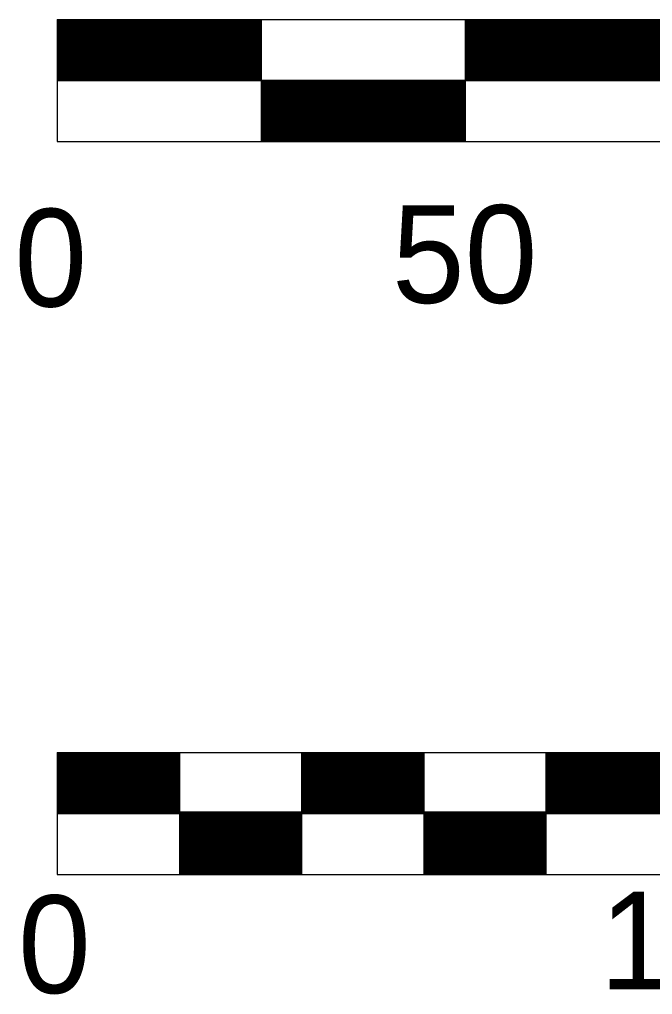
# Model space of a CAD drawing. Extents: x 2147712 to 2176316, y 2125036 to 2131746.
# Drawn here: x 2169958.2 to 2170010, y 2129019.9 to 2129099.7 of the extents above; entities that cross this region are included whole.
import ezdxf

# ---------------------------------------------------------------- set-up
doc = ezdxf.new("R2010")
doc.units = 0
doc.layers.add('MAP DATA', color=7, linetype='Continuous')

msp = doc.modelspace()

# ---------------------------------------------------------------- linework, layer by layer
at = {"layer": 'MAP DATA'}
for p, q in [((2169961.289, 2129099.718), (2170461.289, 2129099.718)), ((2169961.289, 2129099.718), (2169961.289, 2129089.718)), ((2169961.289, 2129099.618), (2169977.989, 2129099.618)), ((2169961.289, 2129099.518), (2169977.989, 2129099.518)), ((2169961.289, 2129099.418), (2169977.989, 2129099.418)), ((2169961.289, 2129099.318), (2169977.989, 2129099.318)), ((2169961.289, 2129099.218), (2169977.989, 2129099.218)), ((2169977.989, 2129099.718), (2169977.989, 2129089.718)), ((2169994.689, 2129099.718), (2169994.689, 2129089.718)), ((2169994.689, 2129099.718), (2170011.289, 2129099.718)), ((2169994.689, 2129099.618), (2170011.289, 2129099.618)), ((2169994.689, 2129099.518), (2170011.289, 2129099.518)), ((2169994.689, 2129099.418), (2170011.289, 2129099.418)), ((2169994.689, 2129099.318), (2170011.289, 2129099.318)), ((2169994.689, 2129099.218), (2170011.289, 2129099.218)), ((2169961.289, 2129099.118), (2169977.989, 2129099.118)), ((2169961.289, 2129099.018), (2169977.989, 2129099.018)), ((2169961.289, 2129098.918), (2169977.989, 2129098.918)), ((2169961.289, 2129098.818), (2169977.989, 2129098.818)), ((2169961.289, 2129098.718), (2169977.989, 2129098.718)), ((2169961.289, 2129098.618), (2169977.989, 2129098.618)), ((2169961.289, 2129098.518), (2169977.989, 2129098.518)), ((2169961.289, 2129098.418), (2169977.989, 2129098.418)), ((2169994.689, 2129099.118), (2170011.289, 2129099.118)), ((2169994.689, 2129099.018), (2170011.289, 2129099.018)), ((2169994.689, 2129098.918), (2170011.289, 2129098.918)), ((2169994.689, 2129098.818), (2170011.289, 2129098.818)), ((2169994.689, 2129098.718), (2170011.289, 2129098.718)), ((2169994.689, 2129098.618), (2170011.289, 2129098.618)), ((2169994.689, 2129098.518), (2170011.289, 2129098.518)), ((2169994.689, 2129098.418), (2170011.289, 2129098.418)), ((2169961.289, 2129098.318), (2169977.989, 2129098.318)), ((2169961.289, 2129098.218), (2169977.989, 2129098.218)), ((2169961.289, 2129098.118), (2169977.989, 2129098.118)), ((2169961.289, 2129098.018), (2169977.989, 2129098.018)), ((2169961.289, 2129097.918), (2169977.989, 2129097.918)), ((2169961.289, 2129097.818), (2169977.989, 2129097.818)), ((2169961.289, 2129097.718), (2169977.989, 2129097.718)), ((2169961.289, 2129097.618), (2169977.989, 2129097.618)), ((2169994.689, 2129098.318), (2170011.289, 2129098.318)), ((2169994.689, 2129098.218), (2170011.289, 2129098.218)), ((2169994.689, 2129098.118), (2170011.289, 2129098.118)), ((2169994.689, 2129098.018), (2170011.289, 2129098.018)), ((2169994.689, 2129097.918), (2170011.289, 2129097.918)), ((2169994.689, 2129097.818), (2170011.289, 2129097.818)), ((2169994.689, 2129097.718), (2170011.289, 2129097.718)), ((2169994.689, 2129097.618), (2170011.289, 2129097.618)), ((2169961.289, 2129097.518), (2169977.989, 2129097.518)), ((2169961.289, 2129097.418), (2169977.989, 2129097.418)), ((2169961.289, 2129097.318), (2169977.989, 2129097.318)), ((2169961.289, 2129097.218), (2169977.989, 2129097.218)), ((2169961.289, 2129097.118), (2169977.989, 2129097.118)), ((2169961.289, 2129097.018), (2169977.989, 2129097.018)), ((2169961.289, 2129096.918), (2169977.989, 2129096.918)), ((2169961.289, 2129096.918), (2169977.989, 2129096.918)), ((2169961.289, 2129096.818), (2169977.989, 2129096.818)), ((2169961.289, 2129096.818), (2169977.989, 2129096.818)), ((2169994.689, 2129097.518), (2170011.289, 2129097.518)), ((2169994.689, 2129097.418), (2170011.289, 2129097.418)), ((2169994.689, 2129097.318), (2170011.289, 2129097.318)), ((2169994.689, 2129097.218), (2170011.289, 2129097.218)), ((2169994.689, 2129097.118), (2170011.289, 2129097.118)), ((2169994.689, 2129097.018), (2170011.289, 2129097.018)), ((2169994.689, 2129096.918), (2170011.289, 2129096.918)), ((2169994.689, 2129096.818), (2170011.289, 2129096.818)), ((2169961.289, 2129096.718), (2169977.989, 2129096.718)), ((2169961.289, 2129096.718), (2169977.989, 2129096.718)), ((2169961.289, 2129096.618), (2169977.989, 2129096.618)), ((2169961.289, 2129096.618), (2169977.989, 2129096.618)), ((2169961.289, 2129096.518), (2169977.989, 2129096.518)), ((2169961.289, 2129096.518), (2169977.989, 2129096.518)), ((2169961.289, 2129096.518), (2169977.989, 2129096.518)), ((2169961.289, 2129096.418), (2169977.989, 2129096.418)), ((2169961.289, 2129096.418), (2169977.989, 2129096.418)), ((2169961.289, 2129096.318), (2169977.989, 2129096.318)), ((2169961.289, 2129096.318), (2169977.989, 2129096.318)), ((2169961.289, 2129096.218), (2169977.989, 2129096.218)), ((2169961.289, 2129096.218), (2169977.989, 2129096.218)), ((2169961.289, 2129096.118), (2169977.989, 2129096.118)), ((2169961.289, 2129096.118), (2169977.989, 2129096.118)), ((2169961.289, 2129096.018), (2169977.989, 2129096.018)), ((2169961.289, 2129096.018), (2169977.989, 2129096.018)), ((2169994.689, 2129096.718), (2170011.289, 2129096.718)), ((2169994.689, 2129096.618), (2170011.289, 2129096.618)), ((2169994.689, 2129096.518), (2170011.289, 2129096.518)), ((2169994.689, 2129096.518), (2170011.289, 2129096.518)), ((2169994.689, 2129096.418), (2170011.289, 2129096.418)), ((2169994.689, 2129096.318), (2170011.289, 2129096.318)), ((2169994.689, 2129096.218), (2170011.289, 2129096.218)), ((2169994.689, 2129096.118), (2170011.289, 2129096.118)), ((2169994.689, 2129096.018), (2170011.289, 2129096.018)), ((2169961.289, 2129095.918), (2169977.989, 2129095.918)), ((2169961.289, 2129095.918), (2169977.989, 2129095.918)), ((2169961.289, 2129095.818), (2169977.989, 2129095.818)), ((2169961.289, 2129095.818), (2169977.989, 2129095.818)), ((2169961.289, 2129095.718), (2169977.989, 2129095.718)), ((2169961.289, 2129095.718), (2169977.989, 2129095.718)), ((2169961.289, 2129095.618), (2169977.989, 2129095.618)), ((2169961.289, 2129095.518), (2169977.989, 2129095.518)), ((2169961.289, 2129095.418), (2169977.989, 2129095.418)), ((2169961.289, 2129095.318), (2169977.989, 2129095.318)), ((2169961.289, 2129095.218), (2169977.989, 2129095.218)), ((2169994.689, 2129095.918), (2170011.289, 2129095.918)), ((2169994.689, 2129095.818), (2170011.289, 2129095.818)), ((2169994.689, 2129095.718), (2170011.289, 2129095.718)), ((2169994.689, 2129095.618), (2170011.289, 2129095.618)), ((2169994.689, 2129095.518), (2170011.289, 2129095.518)), ((2169994.689, 2129095.418), (2170011.289, 2129095.418)), ((2169994.689, 2129095.318), (2170011.289, 2129095.318)), ((2169994.689, 2129095.218), (2170011.289, 2129095.218)), ((2169961.289, 2129095.118), (2169977.989, 2129095.118)), ((2169961.289, 2129095.018), (2169977.989, 2129095.018)), ((2169961.289, 2129094.918), (2169977.989, 2129094.918)), ((2169961.289, 2129094.818), (2169977.989, 2129094.818)), ((2169961.289, 2129094.718), (2170027.889, 2129094.718)), ((2169994.689, 2129094.718), (2169977.989, 2129094.718)), ((2169994.689, 2129094.618), (2169977.989, 2129094.618)), ((2169994.689, 2129094.518), (2169977.989, 2129094.518)), ((2169994.689, 2129094.518), (2169977.989, 2129094.518)), ((2169994.689, 2129094.418), (2169977.989, 2129094.418)), ((2169994.689, 2129094.418), (2169977.989, 2129094.418)), ((2169994.689, 2129095.118), (2170011.289, 2129095.118)), ((2169994.689, 2129095.018), (2170011.289, 2129095.018)), ((2169994.689, 2129094.918), (2170011.289, 2129094.918)), ((2169994.689, 2129094.818), (2170011.289, 2129094.818)), ((2169994.689, 2129094.718), (2170011.289, 2129094.718)), ((2169994.689, 2129094.318), (2169977.989, 2129094.318)), ((2169994.689, 2129094.218), (2169977.989, 2129094.218)), ((2169994.689, 2129094.118), (2169977.989, 2129094.118)), ((2169994.689, 2129094.018), (2169977.989, 2129094.018)), ((2169994.689, 2129093.918), (2169977.989, 2129093.918)), ((2169994.689, 2129093.818), (2169977.989, 2129093.818)), ((2169994.689, 2129093.718), (2169977.989, 2129093.718)), ((2169994.689, 2129093.618), (2169977.989, 2129093.618)), ((2169994.689, 2129093.518), (2169977.989, 2129093.518)), ((2169994.689, 2129093.418), (2169977.989, 2129093.418)), ((2169994.689, 2129093.318), (2169977.989, 2129093.318)), ((2169994.689, 2129093.218), (2169977.989, 2129093.218)), ((2169994.689, 2129093.118), (2169977.989, 2129093.118)), ((2169994.689, 2129093.018), (2169977.989, 2129093.018)), ((2169994.689, 2129092.918), (2169977.989, 2129092.918)), ((2169994.689, 2129092.818), (2169977.989, 2129092.818)), ((2169994.689, 2129092.718), (2169977.989, 2129092.718)), ((2169994.689, 2129092.618), (2169977.989, 2129092.618)), ((2169994.689, 2129092.518), (2169977.989, 2129092.518)), ((2169994.689, 2129092.418), (2169977.989, 2129092.418)), ((2169994.689, 2129092.318), (2169977.989, 2129092.318)), ((2169994.689, 2129092.218), (2169977.989, 2129092.218)), ((2169994.689, 2129092.118), (2169977.989, 2129092.118)), ((2169994.689, 2129092.018), (2169977.989, 2129092.018)), ((2169994.689, 2129091.918), (2169977.989, 2129091.918)), ((2169994.689, 2129091.818), (2169977.989, 2129091.818)), ((2169994.689, 2129091.718), (2169977.989, 2129091.718)), ((2169994.689, 2129091.618), (2169977.989, 2129091.618)), ((2169994.689, 2129091.518), (2169977.989, 2129091.518)), ((2169994.689, 2129091.418), (2169977.989, 2129091.418)), ((2169994.689, 2129091.318), (2169977.989, 2129091.318)), ((2169994.689, 2129091.318), (2169977.989, 2129091.318)), ((2169994.689, 2129091.218), (2169977.989, 2129091.218)), ((2169994.689, 2129091.118), (2169977.989, 2129091.118)), ((2169994.689, 2129091.018), (2169977.989, 2129091.018)), ((2169994.689, 2129090.918), (2169977.989, 2129090.918)), ((2169994.689, 2129090.818), (2169977.989, 2129090.818)), ((2169994.689, 2129090.718), (2169977.989, 2129090.718)), ((2169994.689, 2129090.618), (2169977.989, 2129090.618)), ((2169994.689, 2129090.518), (2169977.989, 2129090.518)), ((2169994.689, 2129090.418), (2169977.989, 2129090.418)), ((2169961.289, 2129089.718), (2170461.289, 2129089.718)), ((2169994.689, 2129090.318), (2169977.989, 2129090.318)), ((2169994.689, 2129090.218), (2169977.989, 2129090.218)), ((2169994.689, 2129090.118), (2169977.989, 2129090.118)), ((2169994.689, 2129090.018), (2169977.989, 2129090.018)), ((2169994.689, 2129089.918), (2169977.989, 2129089.918)), ((2169994.689, 2129089.918), (2169977.989, 2129089.918)), ((2169994.689, 2129089.818), (2169977.989, 2129089.818)), ((2169994.689, 2129089.718), (2169977.989, 2129089.718)), ((2169961.289, 2129039.718), (2169961.289, 2129029.718)), ((2169961.289, 2129039.718), (2170461.289, 2129039.718)), ((2169961.289, 2129039.618), (2169971.289, 2129039.618)), ((2169961.289, 2129039.518), (2169971.289, 2129039.518)), ((2169961.289, 2129039.518), (2169971.289, 2129039.518)), ((2169961.289, 2129039.418), (2169971.289, 2129039.418)), ((2169961.289, 2129039.418), (2169971.289, 2129039.418)), ((2169961.289, 2129039.318), (2169971.289, 2129039.318)), ((2169961.289, 2129039.318), (2169971.289, 2129039.318)), ((2169971.289, 2129039.718), (2169971.289, 2129029.718)), ((2169981.289, 2129039.718), (2169981.289, 2129029.718)), ((2169981.289, 2129039.618), (2169991.289, 2129039.618)), ((2169981.289, 2129039.518), (2169991.289, 2129039.518)), ((2169981.289, 2129039.418), (2169991.289, 2129039.418)), ((2169981.289, 2129039.318), (2169991.289, 2129039.318)), ((2169991.289, 2129039.718), (2169991.289, 2129029.718)), ((2170001.289, 2129039.718), (2170001.289, 2129029.718)), ((2170001.289, 2129039.618), (2170011.289, 2129039.618)), ((2170001.289, 2129039.518), (2170011.289, 2129039.518)), ((2170001.289, 2129039.418), (2170011.289, 2129039.418)), ((2170001.289, 2129039.318), (2170011.289, 2129039.318)), ((2169961.289, 2129039.218), (2169971.289, 2129039.218)), ((2169961.289, 2129039.218), (2169971.289, 2129039.218)), ((2169961.289, 2129039.118), (2169971.289, 2129039.118)), ((2169961.289, 2129039.018), (2169971.289, 2129039.018)), ((2169961.289, 2129038.918), (2169971.289, 2129038.918)), ((2169961.289, 2129038.818), (2169971.289, 2129038.818)), ((2169961.289, 2129038.718), (2169971.289, 2129038.718)), ((2169961.289, 2129038.618), (2169971.289, 2129038.618)), ((2169961.289, 2129038.518), (2169971.289, 2129038.518)), ((2169981.289, 2129039.218), (2169991.289, 2129039.218)), ((2169981.289, 2129039.118), (2169991.289, 2129039.118)), ((2169981.289, 2129039.018), (2169991.289, 2129039.018)), ((2169981.289, 2129038.918), (2169991.289, 2129038.918)), ((2169981.289, 2129038.818), (2169991.289, 2129038.818)), ((2169981.289, 2129038.718), (2169991.289, 2129038.718)), ((2169981.289, 2129038.618), (2169991.289, 2129038.618)), ((2169981.289, 2129038.518), (2169991.289, 2129038.518)), ((2170001.289, 2129039.218), (2170011.289, 2129039.218)), ((2170001.289, 2129039.118), (2170011.289, 2129039.118)), ((2170001.289, 2129039.018), (2170011.289, 2129039.018)), ((2170001.289, 2129038.918), (2170011.289, 2129038.918)), ((2170001.289, 2129038.818), (2170011.289, 2129038.818)), ((2170001.289, 2129038.718), (2170011.289, 2129038.718)), ((2170001.289, 2129038.618), (2170011.289, 2129038.618)), ((2170001.289, 2129038.518), (2170011.289, 2129038.518)), ((2169961.289, 2129038.418), (2169971.289, 2129038.418)), ((2169961.289, 2129038.318), (2169971.289, 2129038.318)), ((2169961.289, 2129038.218), (2169971.289, 2129038.218)), ((2169961.289, 2129038.118), (2169971.289, 2129038.118)), ((2169961.289, 2129038.018), (2169971.289, 2129038.018)), ((2169961.289, 2129037.918), (2169971.289, 2129037.918)), ((2169961.289, 2129037.818), (2169971.289, 2129037.818)), ((2169961.289, 2129037.718), (2169971.289, 2129037.718)), ((2169981.289, 2129038.418), (2169991.289, 2129038.418)), ((2169981.289, 2129038.318), (2169991.289, 2129038.318)), ((2169981.289, 2129038.218), (2169991.289, 2129038.218)), ((2169981.289, 2129038.118), (2169991.289, 2129038.118)), ((2169981.289, 2129038.018), (2169991.289, 2129038.018)), ((2169981.289, 2129037.918), (2169991.289, 2129037.918)), ((2169981.289, 2129037.818), (2169991.289, 2129037.818)), ((2169981.289, 2129037.718), (2169991.289, 2129037.718)), ((2170001.289, 2129038.418), (2170011.289, 2129038.418)), ((2170001.289, 2129038.318), (2170011.289, 2129038.318)), ((2170001.289, 2129038.218), (2170011.289, 2129038.218)), ((2170001.289, 2129038.118), (2170011.289, 2129038.118)), ((2170001.289, 2129038.018), (2170011.289, 2129038.018)), ((2170001.289, 2129037.918), (2170011.289, 2129037.918)), ((2170001.289, 2129037.818), (2170011.289, 2129037.818)), ((2170001.289, 2129037.718), (2170011.289, 2129037.718)), ((2169961.289, 2129037.618), (2169971.289, 2129037.618)), ((2169961.289, 2129037.518), (2169971.289, 2129037.518)), ((2169961.289, 2129037.418), (2169971.289, 2129037.418)), ((2169961.289, 2129037.318), (2169971.289, 2129037.318)), ((2169961.289, 2129037.218), (2169971.289, 2129037.218)), ((2169961.289, 2129037.118), (2169971.289, 2129037.118)), ((2169961.289, 2129037.018), (2169971.289, 2129037.018)), ((2169961.289, 2129036.918), (2169971.289, 2129036.918)), ((2169981.289, 2129037.618), (2169991.289, 2129037.618)), ((2169981.289, 2129037.518), (2169991.289, 2129037.518)), ((2169981.289, 2129037.418), (2169991.289, 2129037.418)), ((2169981.289, 2129037.318), (2169991.289, 2129037.318)), ((2169981.289, 2129037.218), (2169991.289, 2129037.218)), ((2169981.289, 2129037.118), (2169991.289, 2129037.118)), ((2169981.289, 2129037.018), (2169991.289, 2129037.018)), ((2169981.289, 2129036.918), (2169991.289, 2129036.918)), ((2170001.289, 2129037.618), (2170011.289, 2129037.618)), ((2170001.289, 2129037.518), (2170011.289, 2129037.518)), ((2170001.289, 2129037.418), (2170011.289, 2129037.418)), ((2170001.289, 2129037.318), (2170011.289, 2129037.318)), ((2170001.289, 2129037.218), (2170011.289, 2129037.218)), ((2170001.289, 2129037.118), (2170011.289, 2129037.118)), ((2170001.289, 2129037.018), (2170011.289, 2129037.018)), ((2170001.289, 2129036.918), (2170011.289, 2129036.918)), ((2169961.289, 2129036.818), (2169971.289, 2129036.818)), ((2169961.289, 2129036.718), (2169971.289, 2129036.718)), ((2169961.289, 2129036.618), (2169971.289, 2129036.618)), ((2169961.289, 2129036.518), (2169971.289, 2129036.518)), ((2169961.289, 2129036.518), (2169971.289, 2129036.518)), ((2169961.289, 2129036.418), (2169971.289, 2129036.418)), ((2169961.289, 2129036.318), (2169971.289, 2129036.318)), ((2169961.289, 2129036.218), (2169971.289, 2129036.218)), ((2169961.289, 2129036.118), (2169971.289, 2129036.118)), ((2169981.289, 2129036.818), (2169991.289, 2129036.818)), ((2169981.289, 2129036.718), (2169991.289, 2129036.718)), ((2169981.289, 2129036.618), (2169991.289, 2129036.618)), ((2169981.289, 2129036.518), (2169991.289, 2129036.518)), ((2169981.289, 2129036.518), (2169991.289, 2129036.518)), ((2169981.289, 2129036.418), (2169991.289, 2129036.418)), ((2169981.289, 2129036.318), (2169991.289, 2129036.318)), ((2169981.289, 2129036.218), (2169991.289, 2129036.218)), ((2169981.289, 2129036.118), (2169991.289, 2129036.118)), ((2170001.289, 2129036.818), (2170011.289, 2129036.818)), ((2170001.289, 2129036.718), (2170011.289, 2129036.718)), ((2170001.289, 2129036.618), (2170011.289, 2129036.618)), ((2170001.289, 2129036.518), (2170011.289, 2129036.518)), ((2170001.289, 2129036.518), (2170011.289, 2129036.518)), ((2170001.289, 2129036.418), (2170011.289, 2129036.418)), ((2170001.289, 2129036.318), (2170011.289, 2129036.318)), ((2170001.289, 2129036.218), (2170011.289, 2129036.218)), ((2170001.289, 2129036.118), (2170011.289, 2129036.118)), ((2169961.289, 2129036.018), (2169971.289, 2129036.018)), ((2169961.289, 2129035.918), (2169971.289, 2129035.918)), ((2169961.289, 2129035.818), (2169971.289, 2129035.818)), ((2169961.289, 2129035.718), (2169971.289, 2129035.718)), ((2169961.289, 2129035.618), (2169971.289, 2129035.618)), ((2169961.289, 2129035.518), (2169971.289, 2129035.518)), ((2169961.289, 2129035.418), (2169971.289, 2129035.418)), ((2169961.289, 2129035.318), (2169971.289, 2129035.318)), ((2169981.289, 2129036.018), (2169991.289, 2129036.018)), ((2169981.289, 2129035.918), (2169991.289, 2129035.918)), ((2169981.289, 2129035.818), (2169991.289, 2129035.818)), ((2169981.289, 2129035.718), (2169991.289, 2129035.718)), ((2169981.289, 2129035.618), (2169991.289, 2129035.618)), ((2169981.289, 2129035.518), (2169991.289, 2129035.518)), ((2169981.289, 2129035.418), (2169991.289, 2129035.418)), ((2169981.289, 2129035.318), (2169991.289, 2129035.318)), ((2170001.289, 2129036.018), (2170011.289, 2129036.018)), ((2170001.289, 2129035.918), (2170011.289, 2129035.918)), ((2170001.289, 2129035.818), (2170011.289, 2129035.818)), ((2170001.289, 2129035.718), (2170011.289, 2129035.718)), ((2170001.289, 2129035.618), (2170011.289, 2129035.618)), ((2170001.289, 2129035.518), (2170011.289, 2129035.518)), ((2170001.289, 2129035.418), (2170011.289, 2129035.418)), ((2170001.289, 2129035.318), (2170011.289, 2129035.318)), ((2169961.289, 2129035.218), (2169971.289, 2129035.218)), ((2169961.289, 2129035.118), (2169971.289, 2129035.118)), ((2169961.289, 2129035.018), (2169971.289, 2129035.018)), ((2169961.289, 2129034.918), (2169971.289, 2129034.918)), ((2169961.289, 2129034.818), (2169971.289, 2129034.818)), ((2169961.289, 2129034.718), (2170461.289, 2129034.718)), ((2169981.289, 2129034.818), (2169971.289, 2129034.818)), ((2169981.289, 2129034.718), (2169971.289, 2129034.718)), ((2169981.289, 2129034.618), (2169971.289, 2129034.618)), ((2169981.289, 2129034.518), (2169971.289, 2129034.518)), ((2169981.289, 2129035.218), (2169991.289, 2129035.218)), ((2169981.289, 2129035.118), (2169991.289, 2129035.118)), ((2169981.289, 2129035.018), (2169991.289, 2129035.018)), ((2169981.289, 2129034.918), (2169991.289, 2129034.918)), ((2169981.289, 2129034.818), (2169991.289, 2129034.818)), ((2169981.289, 2129034.718), (2169991.289, 2129034.718)), ((2170001.289, 2129034.818), (2169991.289, 2129034.818)), ((2170001.289, 2129034.718), (2169991.289, 2129034.718)), ((2170001.289, 2129034.618), (2169991.289, 2129034.618)), ((2170001.289, 2129034.518), (2169991.289, 2129034.518)), ((2170001.289, 2129035.218), (2170011.289, 2129035.218)), ((2170001.289, 2129035.118), (2170011.289, 2129035.118)), ((2170001.289, 2129035.018), (2170011.289, 2129035.018)), ((2170001.289, 2129034.918), (2170011.289, 2129034.918)), ((2170001.289, 2129034.818), (2170011.289, 2129034.818)), ((2170001.289, 2129034.718), (2170011.289, 2129034.718)), ((2169981.289, 2129034.418), (2169971.289, 2129034.418)), ((2169981.289, 2129034.318), (2169971.289, 2129034.318)), ((2169981.289, 2129034.218), (2169971.289, 2129034.218)), ((2169981.289, 2129034.118), (2169971.289, 2129034.118)), ((2169981.289, 2129034.018), (2169971.289, 2129034.018)), ((2169981.289, 2129033.918), (2169971.289, 2129033.918)), ((2169981.289, 2129033.818), (2169971.289, 2129033.818)), ((2169981.289, 2129033.718), (2169971.289, 2129033.718)), ((2170001.289, 2129034.418), (2169991.289, 2129034.418)), ((2170001.289, 2129034.318), (2169991.289, 2129034.318)), ((2170001.289, 2129034.218), (2169991.289, 2129034.218)), ((2170001.289, 2129034.118), (2169991.289, 2129034.118)), ((2170001.289, 2129034.018), (2169991.289, 2129034.018)), ((2170001.289, 2129033.918), (2169991.289, 2129033.918)), ((2170001.289, 2129033.818), (2169991.289, 2129033.818)), ((2170001.289, 2129033.718), (2169991.289, 2129033.718)), ((2169981.289, 2129033.618), (2169971.289, 2129033.618)), ((2169981.289, 2129033.518), (2169971.289, 2129033.518)), ((2169981.289, 2129033.418), (2169971.289, 2129033.418)), ((2169981.289, 2129033.318), (2169971.289, 2129033.318)), ((2169981.289, 2129033.218), (2169971.289, 2129033.218)), ((2169981.289, 2129033.118), (2169971.289, 2129033.118)), ((2169981.289, 2129033.018), (2169971.289, 2129033.018)), ((2169981.289, 2129032.918), (2169971.289, 2129032.918)), ((2170001.289, 2129033.618), (2169991.289, 2129033.618)), ((2170001.289, 2129033.518), (2169991.289, 2129033.518)), ((2170001.289, 2129033.418), (2169991.289, 2129033.418)), ((2170001.289, 2129033.318), (2169991.289, 2129033.318)), ((2170001.289, 2129033.218), (2169991.289, 2129033.218)), ((2170001.289, 2129033.118), (2169991.289, 2129033.118)), ((2170001.289, 2129033.018), (2169991.289, 2129033.018)), ((2170001.289, 2129032.918), (2169991.289, 2129032.918)), ((2169981.289, 2129032.818), (2169971.289, 2129032.818)), ((2169981.289, 2129032.718), (2169971.289, 2129032.718)), ((2169981.289, 2129032.618), (2169971.289, 2129032.618)), ((2169981.289, 2129032.518), (2169971.289, 2129032.518)), ((2169981.289, 2129032.418), (2169971.289, 2129032.418)), ((2169981.289, 2129032.318), (2169971.289, 2129032.318)), ((2169981.289, 2129032.218), (2169971.289, 2129032.218)), ((2169981.289, 2129032.118), (2169971.289, 2129032.118)), ((2170001.289, 2129032.818), (2169991.289, 2129032.818)), ((2170001.289, 2129032.718), (2169991.289, 2129032.718)), ((2170001.289, 2129032.618), (2169991.289, 2129032.618)), ((2170001.289, 2129032.518), (2169991.289, 2129032.518)), ((2170001.289, 2129032.418), (2169991.289, 2129032.418)), ((2170001.289, 2129032.318), (2169991.289, 2129032.318)), ((2170001.289, 2129032.218), (2169991.289, 2129032.218)), ((2170001.289, 2129032.118), (2169991.289, 2129032.118)), ((2169981.289, 2129032.018), (2169971.289, 2129032.018)), ((2169981.289, 2129031.918), (2169971.289, 2129031.918)), ((2169981.289, 2129031.818), (2169971.289, 2129031.818)), ((2169981.289, 2129031.718), (2169971.289, 2129031.718)), ((2169981.289, 2129031.618), (2169971.289, 2129031.618)), ((2169981.289, 2129031.518), (2169971.289, 2129031.518)), ((2169981.289, 2129031.418), (2169971.289, 2129031.418)), ((2169981.289, 2129031.318), (2169971.289, 2129031.318)), ((2169981.289, 2129031.318), (2169971.289, 2129031.318)), ((2170001.289, 2129032.018), (2169991.289, 2129032.018)), ((2170001.289, 2129031.918), (2169991.289, 2129031.918)), ((2170001.289, 2129031.818), (2169991.289, 2129031.818)), ((2170001.289, 2129031.718), (2169991.289, 2129031.718)), ((2170001.289, 2129031.618), (2169991.289, 2129031.618)), ((2170001.289, 2129031.518), (2169991.289, 2129031.518)), ((2170001.289, 2129031.418), (2169991.289, 2129031.418)), ((2170001.289, 2129031.318), (2169991.289, 2129031.318)), ((2170001.289, 2129031.318), (2169991.289, 2129031.318)), ((2169981.289, 2129031.218), (2169971.289, 2129031.218)), ((2169981.289, 2129031.118), (2169971.289, 2129031.118)), ((2169981.289, 2129031.018), (2169971.289, 2129031.018)), ((2169981.289, 2129030.918), (2169971.289, 2129030.918)), ((2169981.289, 2129030.818), (2169971.289, 2129030.818)), ((2169981.289, 2129030.718), (2169971.289, 2129030.718)), ((2169981.289, 2129030.618), (2169971.289, 2129030.618)), ((2169981.289, 2129030.518), (2169971.289, 2129030.518)), ((2170001.289, 2129031.218), (2169991.289, 2129031.218)), ((2170001.289, 2129031.118), (2169991.289, 2129031.118)), ((2170001.289, 2129031.018), (2169991.289, 2129031.018)), ((2170001.289, 2129030.918), (2169991.289, 2129030.918)), ((2170001.289, 2129030.818), (2169991.289, 2129030.818)), ((2170001.289, 2129030.718), (2169991.289, 2129030.718)), ((2170001.289, 2129030.618), (2169991.289, 2129030.618)), ((2170001.289, 2129030.518), (2169991.289, 2129030.518)), ((2169961.289, 2129029.718), (2170461.289, 2129029.718)), ((2169981.289, 2129030.418), (2169971.289, 2129030.418)), ((2169981.289, 2129030.318), (2169971.289, 2129030.318)), ((2169981.289, 2129030.218), (2169971.289, 2129030.218)), ((2169981.289, 2129030.118), (2169971.289, 2129030.118)), ((2169981.289, 2129030.018), (2169971.289, 2129030.018)), ((2169981.289, 2129029.918), (2169971.289, 2129029.918)), ((2169981.289, 2129029.818), (2169971.289, 2129029.818)), ((2169981.289, 2129029.718), (2169971.289, 2129029.718)), ((2170001.289, 2129030.418), (2169991.289, 2129030.418)), ((2170001.289, 2129030.318), (2169991.289, 2129030.318)), ((2170001.289, 2129030.218), (2169991.289, 2129030.218)), ((2170001.289, 2129030.118), (2169991.289, 2129030.118)), ((2170001.289, 2129030.018), (2169991.289, 2129030.018)), ((2170001.289, 2129029.918), (2169991.289, 2129029.918)), ((2170001.289, 2129029.818), (2169991.289, 2129029.818)), ((2170001.289, 2129029.718), (2169991.289, 2129029.718))]:
    msp.add_line(p, q, dxfattribs=at)

# ---------------------------------------------------------------- texts
for s, height, p in [('0', 8, (2169957.789, 2129076.218)), ('50', 7.9998, (2169988.689, 2129076.518)), ('0', 8, (2169958.089, 2129020.018)), ('100', 7.9998, (2170005.689, 2129020.318))]:
    msp.add_text(s, height=height, dxfattribs=at).set_placement(p)

doc.saveas('drawing.dxf')
